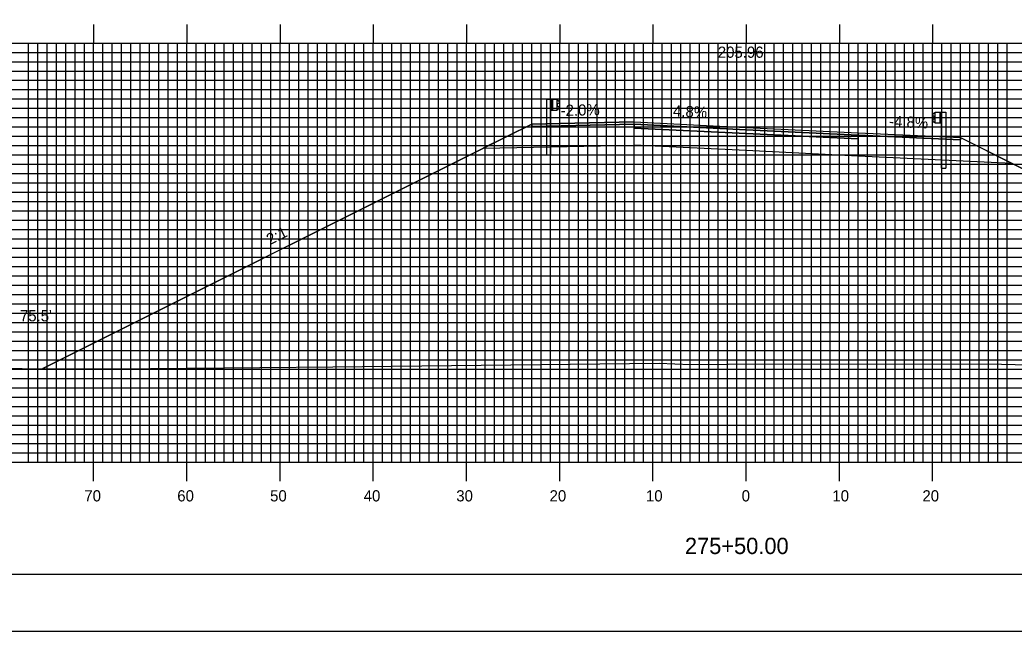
# Model space of a CAD drawing. Extents: x 1809800 to 1810143, y 442591 to 442811.
# Drawn here: x 1809887.4 to 1809994.1, y 442590.5 to 442656.2 of the extents above; entities that cross this region are included whole.
import ezdxf

# ---------------------------------------------------------------- set-up
doc = ezdxf.new("R2010")
doc.units = 0
for name, color, linetype in [('ANNOTATION', 7, 'Continuous'), ('BORDER', 7, 'Continuous'), ('D_Guardrail_Beam_Lt', 7, 'Continuous'), ('D_Guardrail_Beam_Rt', 7, 'Continuous'), ('D_Roadway_Centerline', 7, 'Continuous'), ('D_Roadway_Centerline_Text', 7, 'Continuous'), ('D_Roadway_Edge_Shoulder', 7, 'Continuous'), ('D_Roadway_Edge_TW', 7, 'Continuous'), ('D_Roadway_Pavement', 7, 'Continuous'), ('D_Roadway_SlopeLines', 7, 'Continuous'), ('D_Roadway_SubGrade', 7, 'Continuous'), ('D_Text_Standard', 7, 'Continuous'), ('H_V ANNOTATION', 7, 'Continuous'), ('MAJOR', 7, 'Continuous'), ('MINOR', 7, 'Continuous'), ('PLOT BOUNDARY', 7, 'Continuous'), ('S_Roadway_Centerline', 7, 'Continuous')]:
    doc.layers.add(name, color=color, linetype=linetype)

msp = doc.modelspace()

# ---------------------------------------------------------------- linework, layer by layer
at = {"layer": 'BORDER'}
msp.add_lwpolyline([(1809815.75, 442596.67), (1810135.75, 442596.67), (1810135.75, 442806.67), (1809815.75, 442806.67)], close=True, dxfattribs=at)
at = {"layer": 'D_Guardrail_Beam_Lt'}
for p, q in [((1809943.92, 442647.62), (1809943.92, 442641.62)), ((1809944.39, 442647.62), (1809943.92, 442647.62)), ((1809945.08, 442647.62), (1809944.39, 442647.62)), ((1809944.39, 442647.62), (1809944.39, 442646.45)), ((1809944.45, 442647.62), (1809944.45, 442646.45)), ((1809944.56, 442647.62), (1809944.56, 442646.45)), ((1809945.08, 442646.45), (1809945.08, 442647.62)), ((1809945.08, 442647.54), (1809945.15, 442647.52)), ((1809945.31, 442647.27), (1809945.12, 442647.14)), ((1809945.17, 442647.51), (1809945.31, 442647.41)), ((1809944.39, 442646.45), (1809945.08, 442646.45)), ((1809944.41, 442641.62), (1809944.41, 442646.45)), ((1809945.08, 442647.07), (1809945.08, 442647)), ((1809945.15, 442646.55), (1809945.08, 442646.54)), ((1809945.12, 442646.94), (1809945.31, 442646.8)), ((1809945.31, 442646.66), (1809945.17, 442646.56)), ((1809944.41, 442641.62), (1809943.92, 442641.62))]:
    msp.add_line(p, q, dxfattribs=at)
for centre, major_axis, start_param, end_param in [((1809945.15, 442647.48), (0.0417, 0), 0.959931, 1.376053), ((1809945.26, 442647.34), (0.0877, 0), 5.323254, 7.243116), ((1809945.16, 442647.07), (-0.0789, 0), 5.323254, 6.283185), ((1809945.16, 442647), (-0.0789, 0), 6.283185, 7.243116), ((1809945.15, 442646.59), (0.0417, 0), 4.907132, 5.323254), ((1809945.26, 442646.73), (0.0877, 0), 5.323254, 7.243116)]:
    msp.add_ellipse(centre, major_axis=major_axis, ratio=0.995501, start_param=start_param, end_param=end_param, dxfattribs=at)
at = {"layer": 'D_Guardrail_Beam_Rt'}
for p, q in [((1809985.53, 442646.14), (1809985.39, 442646.04)), ((1809985.62, 442646.16), (1809985.55, 442646.15)), ((1809985.62, 442646.24), (1809986.31, 442646.24)), ((1809985.62, 442645.08), (1809985.62, 442646.24)), ((1809986.14, 442646.24), (1809986.14, 442645.08)), ((1809986.25, 442646.24), (1809986.25, 442645.08)), ((1809986.31, 442646.24), (1809986.78, 442646.24)), ((1809986.31, 442646.24), (1809986.31, 442645.08)), ((1809986.78, 442646.24), (1809986.78, 442640.24)), ((1809985.39, 442645.9), (1809985.58, 442645.76)), ((1809985.58, 442645.56), (1809985.39, 442645.42)), ((1809985.39, 442645.28), (1809985.53, 442645.18)), ((1809985.55, 442645.17), (1809985.62, 442645.16)), ((1809985.62, 442645.7), (1809985.62, 442645.63)), ((1809986.31, 442645.08), (1809985.62, 442645.08)), ((1809986.29, 442640.24), (1809986.29, 442645.08)), ((1809986.29, 442640.24), (1809986.78, 442640.24))]:
    msp.add_line(p, q, dxfattribs=at)
for centre, major_axis, start_param, end_param in [((1809985.56, 442646.1), (-0.0417, 0), 4.907132, 5.323254), ((1809985.44, 442645.97), (-0.0877, 0), 5.323254, 7.243116), ((1809985.44, 442645.35), (-0.0877, 0), 5.323254, 7.243116), ((1809985.56, 442645.22), (-0.0417, 0), 0.959931, 1.376053), ((1809985.54, 442645.7), (0.0789, 0), 0, 0.959931), ((1809985.54, 442645.63), (0.0789, 0), 5.323254, 6.283185)]:
    msp.add_ellipse(centre, major_axis=major_axis, ratio=0.995501, start_param=start_param, end_param=end_param, dxfattribs=at)
at = {"layer": 'D_Roadway_Centerline'}
msp.add_lwpolyline([(1809889.88, 442618.74), (1809937.14, 442642.37), (1809942.35, 442644.98), (1809945.35, 442645.04), (1809953.35, 442645.2), (1809965.35, 442644.62), (1809977.35, 442644.04), (1809985.35, 442643.66), (1809988.35, 442643.52), (1809993.88, 442640.75), (1810038.12, 442618.63)], dxfattribs=at)
at = {"layer": 'D_Roadway_Edge_Shoulder'}
for points in [[(1809953.35, 442645.2), (1809945.35, 442645.04), (1809945.35, 442645.04), (1809942.35, 442644.98), (1809942.35, 442644.73), (1809953.35, 442644.95)], [(1809977.35, 442644.04), (1809985.35, 442643.66), (1809985.35, 442643.66), (1809988.35, 442643.52), (1809988.35, 442643.27), (1809977.35, 442643.79)]]:
    msp.add_lwpolyline(points, close=True, dxfattribs=at)
at = {"layer": 'D_Roadway_Edge_TW'}
msp.add_lwpolyline([(1809953.35, 442644.95), (1809953.35, 442645.2), (1809965.35, 442644.62), (1809977.35, 442644.04), (1809977.35, 442643.79), (1809965.35, 442644.37)], close=True, dxfattribs=at)
at = {"layer": 'D_Roadway_Pavement'}
msp.add_lwpolyline([(1809953.35, 442644.53), (1809953.35, 442644.95), (1809965.35, 442644.37), (1809977.35, 442643.79), (1809977.35, 442643.38), (1809965.35, 442643.95)], close=True, dxfattribs=at)
for points in [[(1809953.35, 442644.95), (1809953.35, 442644.53)], [(1809977.35, 442643.79), (1809977.35, 442643.38)]]:
    msp.add_lwpolyline(points, dxfattribs=at)
at = {"layer": 'D_Roadway_SlopeLines'}
for points in [[(1809942.35, 442644.98), (1809889.88, 442618.74)], [(1809988.35, 442643.52), (1810038.12, 442618.63)]]:
    msp.add_lwpolyline(points, dxfattribs=at)
at = {"layer": 'D_Roadway_SubGrade'}
for points in [[(1809953.35, 442644.53), (1809953.35, 442644.95), (1809942.35, 442644.73), (1809942.35, 442644.98), (1809937.14, 442642.37), (1809953.35, 442642.7)], [(1809953.35, 442642.7), (1809953.35, 442644.95), (1809953.35, 442644.53), (1809965.35, 442643.95), (1809977.35, 442643.38), (1809977.35, 442643.79), (1809977.35, 442641.54), (1809965.35, 442642.12)], [(1809977.35, 442643.38), (1809977.35, 442643.79), (1809988.35, 442643.27), (1809988.35, 442643.52), (1809993.88, 442640.75), (1809977.35, 442641.54)]]:
    msp.add_lwpolyline(points, close=True, dxfattribs=at)
at = {"layer": 'MAJOR'}
for p, q in [((1809895.35, 442655.67), (1809895.35, 442653.67)), ((1809905.35, 442655.67), (1809905.35, 442653.67)), ((1809915.35, 442655.67), (1809915.35, 442653.67)), ((1809925.35, 442655.67), (1809925.35, 442653.67)), ((1809935.35, 442655.67), (1809935.35, 442653.67)), ((1809945.35, 442655.67), (1809945.35, 442653.67)), ((1809955.35, 442655.67), (1809955.35, 442653.67)), ((1809965.35, 442655.67), (1809965.35, 442653.67)), ((1809975.35, 442655.67), (1809975.35, 442653.67)), ((1809985.35, 442655.67), (1809985.35, 442653.67)), ((1809825.35, 442653.67), (1810105.35, 442653.67)), ((1809825.35, 442653.67), (1810105.35, 442653.67)), ((1809895.35, 442608.67), (1809895.35, 442653.67)), ((1809905.35, 442608.67), (1809905.35, 442653.67)), ((1809915.35, 442608.67), (1809915.35, 442653.67)), ((1809925.35, 442608.67), (1809925.35, 442653.67)), ((1809935.35, 442608.67), (1809935.35, 442653.67)), ((1809945.35, 442608.67), (1809945.35, 442653.67)), ((1809955.35, 442608.67), (1809955.35, 442653.67)), ((1809965.35, 442608.67), (1809965.35, 442653.67)), ((1809975.35, 442608.67), (1809975.35, 442653.67)), ((1809985.35, 442608.67), (1809985.35, 442653.67)), ((1809825.35, 442648.67), (1810105.35, 442648.67)), ((1809825.35, 442643.67), (1810105.35, 442643.67)), ((1809825.35, 442638.67), (1810105.35, 442638.67)), ((1809825.35, 442633.67), (1810105.35, 442633.67)), ((1809825.35, 442628.67), (1810105.35, 442628.67)), ((1809825.35, 442623.67), (1810105.35, 442623.67)), ((1809825.35, 442618.67), (1810105.35, 442618.67)), ((1809825.35, 442613.67), (1810105.35, 442613.67)), ((1809825.35, 442608.67), (1810105.35, 442608.67)), ((1809825.35, 442608.67), (1810105.35, 442608.67)), ((1809895.35, 442606.66), (1809895.35, 442608.67)), ((1809905.35, 442606.66), (1809905.35, 442608.67)), ((1809915.35, 442606.66), (1809915.35, 442608.67)), ((1809925.35, 442606.66), (1809925.35, 442608.67)), ((1809935.35, 442606.66), (1809935.35, 442608.67)), ((1809945.35, 442606.66), (1809945.35, 442608.67)), ((1809955.35, 442606.66), (1809955.35, 442608.67)), ((1809965.35, 442606.66), (1809965.35, 442608.67)), ((1809975.35, 442606.66), (1809975.35, 442608.67)), ((1809985.35, 442606.66), (1809985.35, 442608.67))]:
    msp.add_line(p, q, dxfattribs=at)
at = {"layer": 'MINOR'}
for p, q in [((1809888.35, 442608.67), (1809888.35, 442653.67)), ((1809889.35, 442608.67), (1809889.35, 442653.67)), ((1809890.35, 442608.67), (1809890.35, 442653.67)), ((1809891.35, 442608.67), (1809891.35, 442653.67)), ((1809892.35, 442608.67), (1809892.35, 442653.67)), ((1809893.35, 442608.67), (1809893.35, 442653.67)), ((1809894.35, 442608.67), (1809894.35, 442653.67)), ((1809896.35, 442608.67), (1809896.35, 442653.67)), ((1809897.35, 442608.67), (1809897.35, 442653.67)), ((1809898.35, 442608.67), (1809898.35, 442653.67)), ((1809899.35, 442608.67), (1809899.35, 442653.67)), ((1809900.35, 442608.67), (1809900.35, 442653.67)), ((1809901.35, 442608.67), (1809901.35, 442653.67)), ((1809902.35, 442608.67), (1809902.35, 442653.67)), ((1809903.35, 442608.67), (1809903.35, 442653.67)), ((1809904.35, 442608.67), (1809904.35, 442653.67)), ((1809906.35, 442608.67), (1809906.35, 442653.67)), ((1809907.35, 442608.67), (1809907.35, 442653.67)), ((1809908.35, 442608.67), (1809908.35, 442653.67)), ((1809909.35, 442608.67), (1809909.35, 442653.67)), ((1809910.35, 442608.67), (1809910.35, 442653.67)), ((1809911.35, 442608.67), (1809911.35, 442653.67)), ((1809912.35, 442608.67), (1809912.35, 442653.67)), ((1809913.35, 442608.67), (1809913.35, 442653.67)), ((1809914.35, 442608.67), (1809914.35, 442653.67)), ((1809916.35, 442608.67), (1809916.35, 442653.67)), ((1809917.35, 442608.67), (1809917.35, 442653.67)), ((1809918.35, 442608.67), (1809918.35, 442653.67)), ((1809919.35, 442608.67), (1809919.35, 442653.67)), ((1809920.35, 442608.67), (1809920.35, 442653.67)), ((1809921.35, 442608.67), (1809921.35, 442653.67)), ((1809922.35, 442608.67), (1809922.35, 442653.67)), ((1809923.35, 442608.67), (1809923.35, 442653.67)), ((1809924.35, 442608.67), (1809924.35, 442653.67)), ((1809926.35, 442608.67), (1809926.35, 442653.67)), ((1809927.35, 442608.67), (1809927.35, 442653.67)), ((1809928.35, 442608.67), (1809928.35, 442653.67)), ((1809929.35, 442608.67), (1809929.35, 442653.67)), ((1809930.35, 442608.67), (1809930.35, 442653.67)), ((1809931.35, 442608.67), (1809931.35, 442653.67)), ((1809932.35, 442608.67), (1809932.35, 442653.67)), ((1809933.35, 442608.67), (1809933.35, 442653.67)), ((1809934.35, 442608.67), (1809934.35, 442653.67)), ((1809936.35, 442608.67), (1809936.35, 442653.67)), ((1809937.35, 442608.67), (1809937.35, 442653.67)), ((1809938.35, 442608.67), (1809938.35, 442653.67)), ((1809939.35, 442608.67), (1809939.35, 442653.67)), ((1809940.35, 442608.67), (1809940.35, 442653.67)), ((1809941.35, 442608.67), (1809941.35, 442653.67)), ((1809942.35, 442608.67), (1809942.35, 442653.67)), ((1809943.35, 442608.67), (1809943.35, 442653.67)), ((1809944.35, 442608.67), (1809944.35, 442653.67)), ((1809946.35, 442608.67), (1809946.35, 442653.67)), ((1809947.35, 442608.67), (1809947.35, 442653.67)), ((1809948.35, 442608.67), (1809948.35, 442653.67)), ((1809949.35, 442608.67), (1809949.35, 442653.67)), ((1809950.35, 442608.67), (1809950.35, 442653.67)), ((1809951.35, 442608.67), (1809951.35, 442653.67)), ((1809952.35, 442608.67), (1809952.35, 442653.67)), ((1809953.35, 442608.67), (1809953.35, 442653.67)), ((1809954.35, 442608.67), (1809954.35, 442653.67)), ((1809956.35, 442608.67), (1809956.35, 442653.67)), ((1809957.35, 442608.67), (1809957.35, 442653.67)), ((1809958.35, 442608.67), (1809958.35, 442653.67)), ((1809959.35, 442608.67), (1809959.35, 442653.67)), ((1809960.35, 442608.67), (1809960.35, 442653.67)), ((1809961.35, 442608.67), (1809961.35, 442653.67)), ((1809962.35, 442608.67), (1809962.35, 442653.67)), ((1809963.35, 442608.67), (1809963.35, 442653.67)), ((1809964.35, 442608.67), (1809964.35, 442653.67)), ((1809966.35, 442608.67), (1809966.35, 442653.67)), ((1809967.35, 442608.67), (1809967.35, 442653.67)), ((1809968.35, 442608.67), (1809968.35, 442653.67)), ((1809969.35, 442608.67), (1809969.35, 442653.67)), ((1809970.35, 442608.67), (1809970.35, 442653.67)), ((1809971.35, 442608.67), (1809971.35, 442653.67)), ((1809972.35, 442608.67), (1809972.35, 442653.67)), ((1809973.35, 442608.67), (1809973.35, 442653.67)), ((1809974.35, 442608.67), (1809974.35, 442653.67)), ((1809976.35, 442608.67), (1809976.35, 442653.67)), ((1809977.35, 442608.67), (1809977.35, 442653.67)), ((1809978.35, 442608.67), (1809978.35, 442653.67)), ((1809979.35, 442608.67), (1809979.35, 442653.67)), ((1809980.35, 442608.67), (1809980.35, 442653.67)), ((1809981.35, 442608.67), (1809981.35, 442653.67)), ((1809982.35, 442608.67), (1809982.35, 442653.67)), ((1809983.35, 442608.67), (1809983.35, 442653.67)), ((1809984.35, 442608.67), (1809984.35, 442653.67)), ((1809986.35, 442608.67), (1809986.35, 442653.67)), ((1809987.35, 442608.67), (1809987.35, 442653.67)), ((1809988.35, 442608.67), (1809988.35, 442653.67)), ((1809989.35, 442608.67), (1809989.35, 442653.67)), ((1809990.35, 442608.67), (1809990.35, 442653.67)), ((1809991.35, 442608.67), (1809991.35, 442653.67)), ((1809992.35, 442608.67), (1809992.35, 442653.67)), ((1809993.35, 442608.67), (1809993.35, 442653.67)), ((1809825.35, 442652.67), (1810105.35, 442652.67)), ((1809825.35, 442651.67), (1810105.35, 442651.67)), ((1809825.35, 442650.67), (1810105.35, 442650.67)), ((1809825.35, 442649.67), (1810105.35, 442649.67)), ((1809825.35, 442647.67), (1810105.35, 442647.67)), ((1809825.35, 442646.67), (1810105.35, 442646.67)), ((1809825.35, 442645.67), (1810105.35, 442645.67)), ((1809825.35, 442644.67), (1810105.35, 442644.67)), ((1809825.35, 442642.67), (1810105.35, 442642.67)), ((1809825.35, 442641.67), (1810105.35, 442641.67)), ((1809825.35, 442640.67), (1810105.35, 442640.67)), ((1809825.35, 442639.67), (1810105.35, 442639.67)), ((1809825.35, 442637.67), (1810105.35, 442637.67)), ((1809825.35, 442636.67), (1810105.35, 442636.67)), ((1809825.35, 442635.67), (1810105.35, 442635.67)), ((1809825.35, 442634.67), (1810105.35, 442634.67)), ((1809825.35, 442632.67), (1810105.35, 442632.67)), ((1809825.35, 442631.67), (1810105.35, 442631.67)), ((1809825.35, 442630.67), (1810105.35, 442630.67)), ((1809825.35, 442629.67), (1810105.35, 442629.67)), ((1809825.35, 442627.67), (1810105.35, 442627.67)), ((1809825.35, 442626.67), (1810105.35, 442626.67)), ((1809825.35, 442625.67), (1810105.35, 442625.67)), ((1809825.35, 442624.67), (1810105.35, 442624.67)), ((1809825.35, 442622.67), (1810105.35, 442622.67)), ((1809825.35, 442621.67), (1810105.35, 442621.67)), ((1809825.35, 442620.67), (1810105.35, 442620.67)), ((1809825.35, 442619.67), (1810105.35, 442619.67)), ((1809825.35, 442617.67), (1810105.35, 442617.67)), ((1809825.35, 442616.67), (1810105.35, 442616.67)), ((1809825.35, 442615.67), (1810105.35, 442615.67)), ((1809825.35, 442614.67), (1810105.35, 442614.67)), ((1809825.35, 442612.67), (1810105.35, 442612.67)), ((1809825.35, 442611.67), (1810105.35, 442611.67)), ((1809825.35, 442610.67), (1810105.35, 442610.67)), ((1809825.35, 442609.67), (1810105.35, 442609.67))]:
    msp.add_line(p, q, dxfattribs=at)
at = {"layer": 'PLOT BOUNDARY'}
msp.add_lwpolyline([(1809799.56, 442590.55), (1810139.56, 442590.55), (1810139.56, 442810.55), (1809799.56, 442810.55)], close=True, dxfattribs=at)
at = {"layer": 'S_Roadway_Centerline'}
msp.add_lwpolyline([(1809825.35, 442617.68), (1809830.33, 442617.73), (1809838.49, 442617.91), (1809868.24, 442618.39), (1809884.81, 442618.77), (1809887.68, 442618.75), (1809897.53, 442618.7), (1809921.01, 442618.91), (1809956.01, 442619.3), (1809959.39, 442619.17), (1809963.41, 442619.2), (1809991.29, 442619.23), (1810016.11, 442618.63), (1810025.9, 442618.65), (1810059.8, 442618.6), (1810084.68, 442618.68), (1810098.88, 442619.31), (1810105.35, 442619.22)], dxfattribs=at)

# ---------------------------------------------------------------- texts
at = {"layer": 'ANNOTATION'}
for s, rotation, p in [('-2.0%', 1.1458, (1809945.46, 442645.84)), ('4.8%', 357.2519, (1809957.48, 442645.8)), ('-4.8%', 357.2519, (1809980.66, 442644.69)), ('2:1', 26.5651, (1809914.26, 442631.97))]:
    msp.add_text(s, height=1.2, rotation=rotation, dxfattribs=at).set_placement(p)
at = {"layer": 'D_Roadway_Centerline'}
for s, p in [('C', (1809965.35, 442644.62)), ('L', (1809965.35, 442644.61))]:
    msp.add_text(s, height=0.0146, dxfattribs=at).set_placement(p)
at = {"layer": 'D_Roadway_Centerline_Text'}
msp.add_text('205.96', height=1.2, dxfattribs=at).set_placement((1809962.31, 442652.09))
at = {"layer": 'D_Text_Standard'}
msp.add_text("75.5'", height=1.2, dxfattribs=at).set_placement((1809887.44, 442623.8))
at = {"layer": 'H_V ANNOTATION'}
for s, height, p in [('70', 1.2, (1809894.35, 442604.47)), ('60', 1.2, (1809904.32, 442604.47)), ('50', 1.2, (1809914.28, 442604.47)), ('40', 1.2, (1809924.32, 442604.47)), ('30', 1.2, (1809934.25, 442604.47)), ('20', 1.2, (1809944.26, 442604.47)), ('10', 1.2, (1809954.6, 442604.47)), ('0', 1.2, (1809964.87, 442604.47)), ('10', 1.2, (1809974.6, 442604.47)), ('20', 1.2, (1809984.26, 442604.47)), ('275+50.00', 1.75, (1809958.78, 442598.82))]:
    msp.add_text(s, height=height, dxfattribs=at).set_placement(p)

doc.saveas('drawing.dxf')
